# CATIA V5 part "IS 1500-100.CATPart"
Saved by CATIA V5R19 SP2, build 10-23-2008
Part number: IS 1500-100
Bounding box of the stored display mesh (mm): x -37.351 to 37.351, y -37.351 to 37.351, z 0 to 310
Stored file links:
  C:\Users\Bora\Desktop\3D Katı model\IS serisi\IS 1500\IS 1500-100.CATPart
  C:\Program Files\Dassault Systemes\B19\intel_a\reffiles\standard\MetricThickPitch.txt
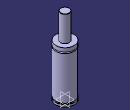
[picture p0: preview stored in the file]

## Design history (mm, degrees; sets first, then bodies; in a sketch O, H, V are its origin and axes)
Body1 (main body)
  Sketch1 on yz-plane, origin (0, 0, 0), H (0, 1, 0), V (0, 0, 1)
    point P1 (37.5, 191.5)
    point P4 (37.5, 186.5)
    point P7 (18, 309)
    point P9 (18, 309)
    point P13 (37.5, 191.5)
    point P14 (37.5, 186.5)
    line L1 (37.5, 191.5) -> (37.5, 207)
    line L2 (37.5, 13) -> (37.5, 186.5)
    line L3 (33.5, 13) -> (33.5, 8)
    arc A1 centre (17, 309) radius 1 from (18, 309) to (17, 310) ccw
    line L4 (18, 309) -> (18, 207)
    line L5 (37.5, 0) -> (37.5, 8)
    arc A2 centre (37.5, 189) radius 2.5 from (37.5, 191.5) to (37.5, 186.5) ccw
    line L6 (17, 310) -> (0, 310)
    point P15 (0, 310)
    line L7 (18, 207) -> (37.5, 207)
    line L8 (0, 0) -> (37.5, 0)
    line L9 (33.5, 8) -> (37.5, 8)
    line L10 (33.5, 13) -> (37.5, 13)
    coincidence: P15 V, P1 P13, P4 P14, P7 P9
    tangency: L6 A1
    horizontal: L7 H, L8 H, L9 H, L10 H
  Shaft1: profile Sketch1, axis Sketch1.V, angle 360
  Sketch2 on face of Shaft1 from Sketch1.L8, origin (0, 0, 0), H (1, 0, 0), V (0, -1, 0)
    point P1 (20, 0)
    distance P1 V = 20
  Hole1: placed by Sketch2, at (20, 0, 0) direction (0, 0, 1), diameter 6.647, depth 13, threaded "M8", thread diameter 8, thread depth 13, pitch 1.25
  CircPattern1: of Hole1, instances 4, angular step 90, axis from xy-plane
